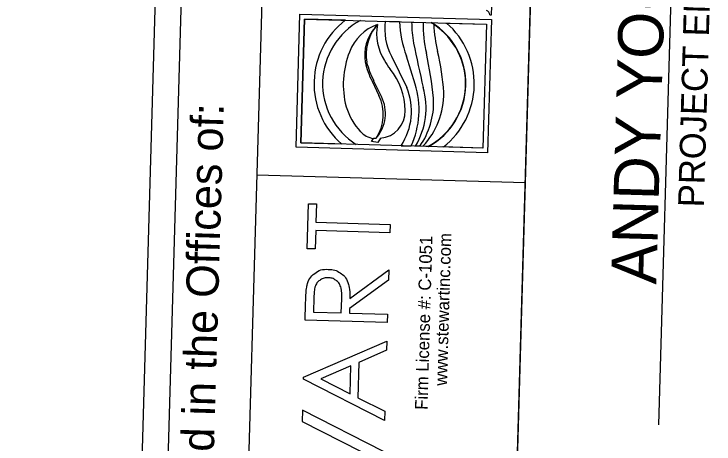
# Model space of a CAD drawing. Extents: x 2097846 to 2099709, y 989477 to 992073.
# Drawn here: x 2099183 to 2099386.1, y 991141.6 to 991266.3 of the extents above; entities that cross this region are included whole.
import ezdxf

# ---------------------------------------------------------------- set-up
doc = ezdxf.new("R2010")
doc.units = 0
for name, color, linetype in [('Sheet Block Title CELL', 7, 'Continuous'), ('Sheet Data Field CELL', 7, 'Continuous'), ('Sheet Title CELL', 7, 'Continuous'), ('Stewart Logo', 7, 'Continuous')]:
    doc.layers.add(name, color=color, linetype=linetype)

msp = doc.modelspace()

# ---------------------------------------------------------------- linework, layer by layer
at = {"layer": 'Sheet Block Title CELL'}
for p, q in [((2099321.58, 991266.04), (2099321.85, 991275.65)), ((2099264.87, 991227.65), (2099265.98, 991266.29)), ((2099265.98, 991266.29), (2099321.55, 991264.69)), ((2099266.28, 991228.96), (2099267.31, 991264.86)), ((2099267.31, 991264.86), (2099266.28, 991228.96)), ((2099267.31, 991264.86), (2099320.13, 991263.34)), ((2099279.19, 991264.52), (2099267.31, 991264.86)), ((2099321.55, 991264.69), (2099320.44, 991226.05)), ((2099321.09, 991266.05), (2099321.58, 991266.04)), ((2099288.49, 991263.3), (2099287.8, 991262.43)), ((2099287.8, 991262.43), (2099288.49, 991263.3)), ((2099294.85, 991264.07), (2099290.72, 991264.19)), ((2099298.39, 991263.97), (2099301.72, 991263.87)), ((2099308.35, 991263.68), (2099320.13, 991263.34)), ((2099320.13, 991263.34), (2099319.09, 991227.44)), ((2099320.13, 991263.34), (2099319.09, 991227.44)), ((2099292.57, 991254.12), (2099297, 991245)), ((2099299.41, 991246.01), (2099296.88, 991254.08)), ((2099286.95, 991246.8), (2099288.89, 991242.65)), ((2099289.62, 991242.35), (2099287.38, 991247.05)), ((2099286.76, 991229.36), (2099287.3, 991230.23)), ((2099288.1, 991230.26), (2099287.3, 991230.23)), ((2099287.3, 991230.23), (2099288.1, 991230.26)), ((2099289.32, 991230.31), (2099288.62, 991229.09)), ((2099319.09, 991227.44), (2099266.28, 991228.96)), ((2099266.28, 991228.96), (2099278.04, 991228.62)), ((2099288.62, 991229.09), (2099286.76, 991229.36)), ((2099295.36, 991228.12), (2099298.24, 991228.05)), ((2099300.78, 991227.97), (2099299.51, 991228)), ((2099303.12, 991227.9), (2099301.66, 991227.94)), ((2099320.44, 991226.05), (2099264.87, 991227.65)), ((2099319.09, 991227.44), (2099307.43, 991227.77))]:
    msp.add_line(p, q, dxfattribs=at)
for centre, radius, start, end in [((2099319.79, 991266.04), 1.29, 0.7147, 75.1162), ((2099293.33, 991246.11), 23.24, 127.6037, 228.7868), ((2099293.33, 991246.11), 20.76, 118.2197, 238.0418), ((2099292.97, 991250.66), 13.41, 109.5008, 159.8174), ((2099296.92, 991254.42), 12.15, 138.7079, 189.9832), ((2099298.89, 991254.4), 13.69, 144.08, 188.5033), ((2099302.6, 991260.63), 14.36, 169.2966, 212.9405), ((2099307.35, 991262.04), 16.77, 172.6225, 208.1931), ((2099328.73, 991265.77), 33.92, 182.8676, 200.1464), ((2099336.56, 991264.43), 38.17, 180.6925, 189.9236), ((2099340.58, 991263.5), 38.86, 179.4467, 192.7096), ((2099293.45, 991246.1), 20.61, 297.9837, 56.544), ((2099293.33, 991246.11), 20.79, 298.6573, 58.4794), ((2099293.45, 991246.1), 20.61, 56.544, 59.2268), ((2099347.29, 991265.31), 42.52, 182.7241, 193.4614), ((2099293.33, 991246.11), 23.24, 307.9123, 49.0954), ((2099613.4, 991320.13), 320.55, 191.203, 193.5588), ((2099303.84, 991245.87), 25.28, 158.1347, 194.7586), ((2099169.82, 991227.26), 135.71, 6.1944, 11.7723), ((2099243.72, 991240.1), 64.07, 3.1143, 13.8318), ((2099306.79, 991257.08), 22.35, 192.3316, 207.4008), ((2099309.62, 991258.63), 25.07, 194.4548, 207.5106), ((2099310.2, 991263.65), 22.44, 208.8496, 216.4501), ((2099277.86, 991238.32), 18.66, 0.0459, 40.0166), ((2099280.08, 991238.13), 18.26, 326.7734, 22.1272), ((2099275.64, 991238.54), 24.92, 335.1008, 17.4335), ((2099280.8, 991239.16), 21.78, 329.1915, 15.5103), ((2099277.39, 991237.17), 12.75, 327.2191, 25.4842), ((2099279.89, 991237.44), 10.91, 318.8866, 26.8117), ((2099285.65, 991243.1), 22.05, 316.5572, 1.2401), ((2099282.57, 991240.68), 22.21, 325.0679, 1.8167), ((2099298, 991241.17), 6.77, 1.8167, 6.1944), ((2099298.83, 991245.75), 20.44, 198.0203, 221.5712), ((2099288.77, 991238.04), 7.75, 274.0157, 2.1478), ((2099288.25, 991236.65), 6.49, 223.4076, 261.531)]:
    msp.add_arc(centre, radius, start, end, dxfattribs=at)
at = {"layer": 'Sheet Title CELL'}
for p, q in [((2099183.04, 989845.97), (2099244.37, 991975.08)), ((2099336.46, 991394.69), (2099328.96, 991134.63)), ((2099222.5, 990955.29), (2099234.81, 991382.61)), ((2099370.1, 991147.17), (2099376.85, 991379.8)), ((2099253.48, 991219.65), (2099331.35, 991217.41))]:
    msp.add_line(p, q, dxfattribs=at)
msp.add_lwpolyline([(2099323.27, 990937.38), (2099336.45, 991394.69), (2099258.59, 991396.94), (2099245.41, 990939.63)], close=True, dxfattribs=at)
at = {"layer": 'Stewart Logo'}
for p, q in [((2099266.72, 991151.39), (2099266.63, 991148.14)), ((2099290.24, 991139.44), (2099266.72, 991151.39)), ((2099266.63, 991148.14), (2099283.58, 991139.53))]:
    msp.add_line(p, q, dxfattribs=at)
for points in [[(2099270.41, 991198.18), (2099268.07, 991198.24), (2099268.45, 991211.3), (2099270.78, 991211.23), (2099270.63, 991205.92), (2099292.14, 991205.3), (2099292.07, 991202.87), (2099270.56, 991203.49), (2099270.41, 991198.18)], [(2099280.45, 991183.84), (2099291.76, 991192.09), (2099291.67, 991189.14), (2099280.36, 991180.89), (2099280.33, 991179.55), (2099291.39, 991179.23), (2099291.32, 991176.86), (2099267.48, 991177.54)], [(2099270, 991184.05), (2099269.88, 991179.85)], [(2099269.88, 991179.85), (2099277.99, 991179.62), (2099278.14, 991183.72)], [(2099267.48, 991177.54), (2099267.61, 991182.28)], [(2099267, 991160.93), (2099291.16, 991171.37), (2099291.09, 991168.79), (2099283.12, 991165.27), (2099282.83, 991155), (2099290.58, 991151.07), (2099290.5, 991148.41), (2099266.98, 991160.35), (2099267, 991160.93)], [(2099272.04, 991160.48), (2099280.56, 991156.15), (2099280.79, 991164.3), (2099272.04, 991160.48)]]:
    msp.add_lwpolyline(points, dxfattribs=at)
for points in [[(2099267.61, 991182.28), (2099267.73, 991186.25), (2099268.09, 991187.65), (2099268.64, 991189.75), (2099270.28, 991191.03), (2099271.92, 991192.31), (2099274.25, 991192.25), (2099276.2, 991192.19), (2099277.66, 991191.23), (2099279.11, 991190.28), (2099279.81, 991188.56), (2099280.52, 991186.83), (2099280.45, 991183.84)], [(2099278.14, 991183.72), (2099278.21, 991186.11), (2099277.79, 991187.26), (2099277.37, 991188.42), (2099276.39, 991189.09), (2099275.41, 991189.76), (2099274.18, 991189.79), (2099272.98, 991189.83), (2099271.98, 991189.21), (2099270.98, 991188.59), (2099270.52, 991187.54), (2099270.07, 991186.5), (2099270, 991184.05)]]:
    msp.add_open_spline(points, degree=3, dxfattribs=at)

# ---------------------------------------------------------------- texts
at = {"layer": 'Sheet Data Field CELL'}
msp.add_text('ANDY YOUNG, PE', height=13.1252, rotation=88.3433, dxfattribs=at).set_placement((2099369.35, 991187.82))
at = {"layer": 'Sheet Title CELL'}
for s, height, rotation, p in [('PROJECT ENGINEER', 7.4993, 88.3433, (2099383.18, 991210.16)), ('Prepared in the Offices of:', 9.375, 88.35, (2099239.74, 991094.68))]:
    msp.add_text(s, height=height, rotation=rotation, dxfattribs=at).set_placement(p)
at = {"layer": 'Stewart Logo'}
for s, p in [('Firm License #: C-1051', (2099302.99, 991151.46)), ('www.stewartinc.com', (2099308.65, 991158.45))]:
    msp.add_text(s, height=3.6351, rotation=88.3496, dxfattribs=at).set_placement(p)

doc.saveas('drawing.dxf')
